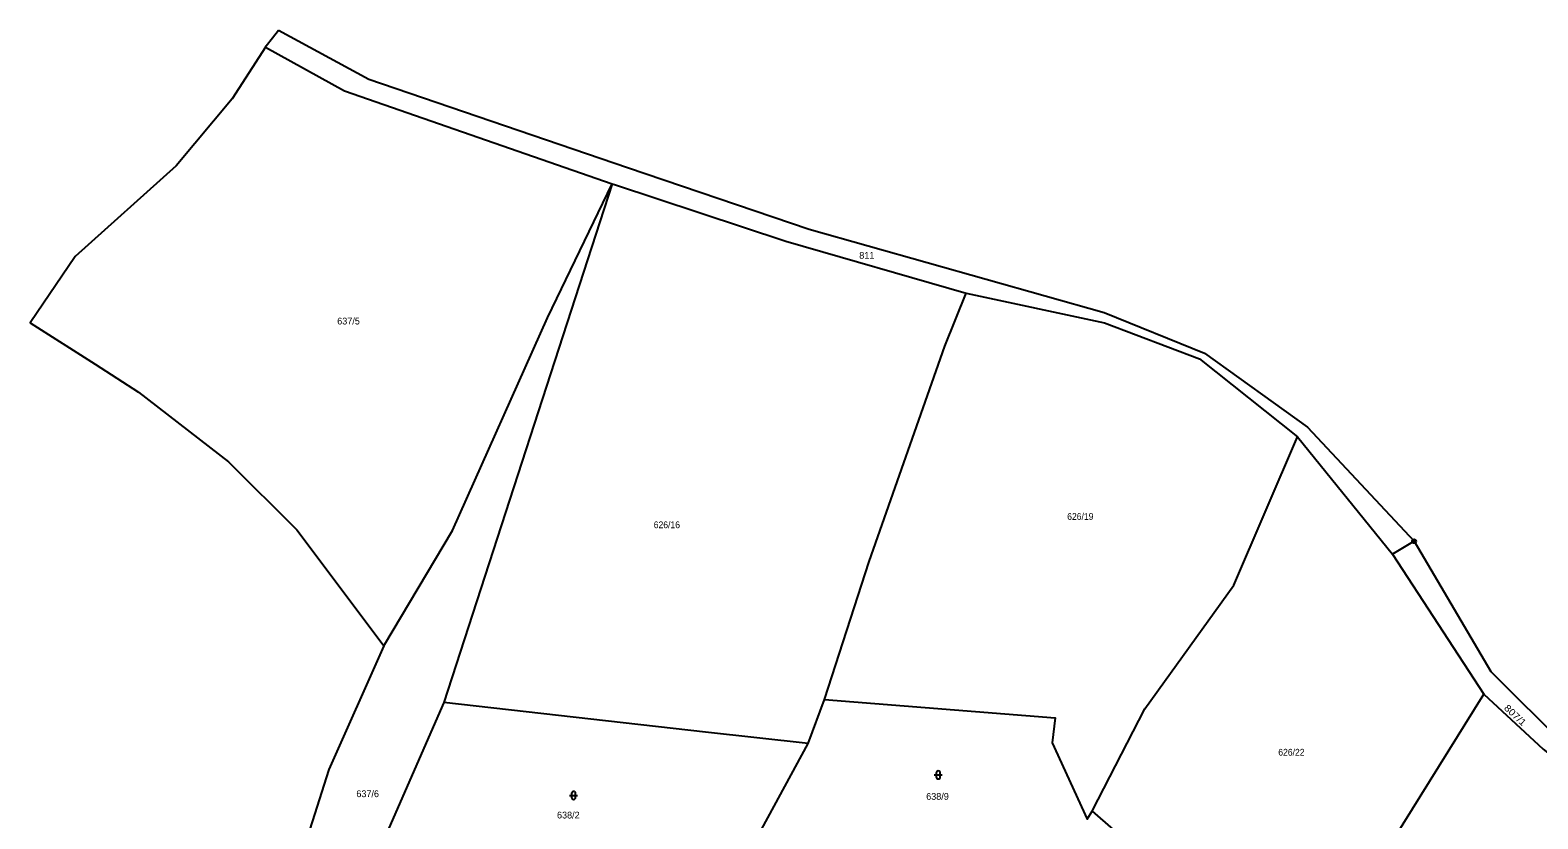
# Model space of a CAD drawing. Extents: x -687135 to -684370, y -1007309 to -1005782.
# Drawn here: x -685290.3 to -684911.1, y -1005980.6 to -1005782.3 of the extents above; entities that cross this region are included whole.
import ezdxf

# ---------------------------------------------------------------- set-up
doc = ezdxf.new("R2010")
doc.units = 0
doc.header["$LTSCALE"] = 0.68
for name, color, linetype, lineweight in [('1', 7, 'Continuous', 25), ('3', 7, 'Continuous', 25), ('8', 7, 'Continuous', 25)]:
    doc.layers.add(name, color=color, linetype=linetype, lineweight=lineweight)
doc.layers.add('2', color=7, linetype='Continuous')

msp = doc.modelspace()

# ---------------------------------------------------------------- linework, layer by layer
at = {"layer": '1'}
for p, q in [((-685229.34, -1005784.18), (-685227.84, -1005782.27)), ((-685143.92, -1005820.89), (-685186.26, -1005951.34)), ((-685094.6, -1005961.65), (-685090.53, -1005950.59))]:
    msp.add_line(p, q, dxfattribs=at)
for points in [[(-685231.17, -1005786.56), (-685230.96, -1005786.24), (-685229.34, -1005784.18)], [(-685227.84, -1005782.27), (-685205.1, -1005794.6), (-685140.07, -1005816.82), (-685094.39, -1005832.29), (-685020.13, -1005853.23), (-684994.95, -1005863.47), (-684969, -1005882.07), (-684942.19, -1005910.78)], [(-685231.17, -1005786.56), (-685239.55, -1005799.57), (-685253.63, -1005816.36)], [(-685231.17, -1005786.56), (-685211.27, -1005797.55), (-685143.92, -1005820.89)], [(-685253.63, -1005816.36), (-685279.03, -1005839.22), (-685290.34, -1005855.88), (-685274, -1005866.29), (-685263.05, -1005873.26), (-685240.46, -1005890.82)], [(-685201.33, -1005937.1), (-685184.09, -1005908.08), (-685160.16, -1005854.58), (-685143.92, -1005820.89)], [(-685143.92, -1005820.89), (-685143.33, -1005821.09), (-685100.25, -1005835.3), (-685054.91, -1005848.36)], [(-685090.53, -1005950.59), (-685079.26, -1005915.91), (-685060.22, -1005861.71), (-685054.91, -1005848.36)], [(-685054.91, -1005848.36), (-685020.11, -1005855.88), (-684996.16, -1005864.94), (-684971.52, -1005884.54), (-684947.61, -1005914.06)], [(-685023.21, -1005978.63), (-685009.92, -1005952.95), (-684987.54, -1005921.78), (-684971.52, -1005884.54)], [(-685240.46, -1005890.82), (-685223.24, -1005907.88), (-685220.88, -1005911.03), (-685201.33, -1005937.1)], [(-684942.19, -1005910.78), (-684947.61, -1005914.06), (-684924.69, -1005949.22)], [(-684942.19, -1005910.78), (-684922.85, -1005943.49), (-684903.97, -1005962.38), (-684866.37, -1005992.78), (-684835.47, -1006012.17), (-684817.9, -1006025.25)], [(-685201.33, -1005937.1), (-685215.2, -1005968.19), (-685237.31, -1006037.69)], [(-685090.53, -1005950.59), (-685032.5, -1005955.2), (-685033.24, -1005961.49), (-685024.44, -1005980.64), (-685023.21, -1005978.63)], [(-684972.24, -1006025.24), (-684958.61, -1006003.79), (-684924.69, -1005949.22)], [(-684924.69, -1005949.22), (-684909.75, -1005963.09), (-684867.33, -1005996.85)], [(-685186.26, -1005951.34), (-685204.26, -1005992.33), (-685219.65, -1006043.93), (-685207.69, -1006048.16)], [(-685094.6, -1005961.65), (-685120.45, -1005958.74), (-685186.26, -1005951.34)], [(-685115.38, -1005999.81), (-685113.34, -1005996.06), (-685094.6, -1005961.65)], [(-685023.21, -1005978.63), (-684999.45, -1005999.31), (-684972.24, -1006025.24)]]:
    msp.add_lwpolyline(points, dxfattribs=at)
at = {"layer": '3'}
for p, q in [((-685062.891, -1005969.541), (-685060.889, -1005969.541)), ((-685062.391, -1005969.041), (-685062.391, -1005970.042)), ((-685061.389, -1005970.042), (-685061.389, -1005969.041)), ((-685154.641, -1005974.681), (-685152.639, -1005974.681)), ((-685154.141, -1005974.181), (-685154.141, -1005975.182)), ((-685153.139, -1005975.182), (-685153.139, -1005974.181))]:
    msp.add_line(p, q, dxfattribs=at)
for centre, start, end in [((-685061.89, -1005969.0409), 0, 180), ((-685061.89, -1005970.0409), 180, 359.98789), ((-685153.64, -1005974.1809), 0, 180), ((-685153.64, -1005975.1809), 180, 359.98789)]:
    msp.add_arc(centre, 0.5, start, end, dxfattribs=at)
at = {"layer": '8'}
for radius in [0.5, 0.0303]:
    msp.add_circle((-684942.19, -1005910.7799), radius, dxfattribs=at)

# ---------------------------------------------------------------- texts
at = {"layer": '2'}
for s, p in [('811', (-685081.77, -1005839.75)), ('637/5', (-685213.09, -1005856.27)), ('637/6', (-685208.28, -1005975.12)), ('638/9', (-685064.93, -1005975.789)), ('638/2', (-685157.8, -1005980.48))]:
    msp.add_text(s, height=1.7, dxfattribs=at).set_placement(p)
at = {"layer": '2', "width": 0.95}
for s, p in [('626/19', (-685029.46, -1005905.4)), ('626/16', (-685133.47, -1005907.49)), ('626/22', (-684976.36, -1005964.679))]:
    msp.add_text(s, height=1.7, dxfattribs=at).set_placement(p)
at = {"layer": '2', "width": 1.15}
msp.add_text('807/1', height=1.7, rotation=317, dxfattribs=at).set_placement((-684919.719, -1005952.911))

doc.saveas('drawing.dxf')
